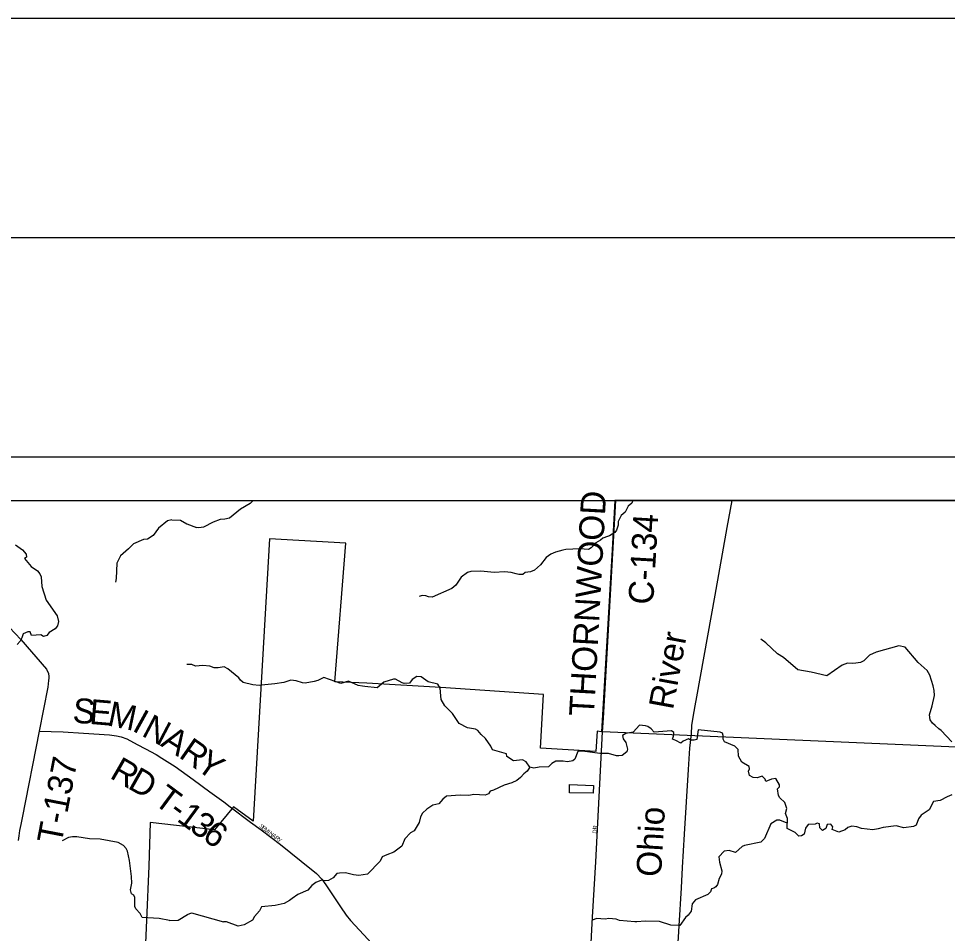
# Model space of a CAD drawing. Extents: x 0 to 40.4, y 0 to 22.
# Drawn here: x 5.767 to 7.886, y 19.912 to 22 of the extents above; entities that cross this region are included whole.
import ezdxf

# ---------------------------------------------------------------- set-up
doc = ezdxf.new("R2010")
doc.units = 0
for name, color, linetype in [('GM_X_City_Street', 7, 'Continuous'), ('GM_X_City_Street_Text', 7, 'Continuous'), ('GM_X_Corporation', 7, 'Continuous'), ('GM_X_County_Road', 7, 'Continuous'), ('GM_X_County_Road_Text', 7, 'Continuous'), ('GM_X_Minor_River', 7, 'Continuous'), ('GM_X_Rail_Line', 7, 'Continuous'), ('GM_X_Rail_Line_Text', 7, 'Continuous'), ('GM_X_Township', 7, 'Continuous'), ('GM_X_Township_Road', 7, 'Continuous'), ('GM_X_Township_Road_Text', 7, 'Continuous'), ('SH_Border', 7, 'Continuous'), ('SH_Cut_Line', 7, 'Continuous'), ('SH_Data', 7, 'Continuous')]:
    doc.layers.add(name, color=color, linetype=linetype)

msp = doc.modelspace()

# ---------------------------------------------------------------- linework, layer by layer
at = {"layer": 'GM_X_City_Street'}
for points in [[(7.0098, 19.1185), (7.0108, 19.1386), (7.0156, 19.1663), (7.0262, 19.2185), (7.0308, 19.2432), (7.0333, 19.26), (7.0351, 19.278), (7.0369, 19.3019), (7.0384, 19.3259), (7.0393, 19.3348), (7.0472, 19.4593), (7.0554, 19.5835), (7.0654, 19.7611), (7.0679, 19.7879), (7.0718, 19.8615), (7.0768, 19.9493), (7.0838, 20.0754), (7.0996, 20.3723), (7.1013, 20.4032)], [(6.2498, 20.2011), (6.296, 20.166), (6.3199, 20.1487), (6.364, 20.1154), (6.4116, 20.0767), (6.4466, 20.0492), (6.4587, 20.036), (6.4681, 20.0231), (6.4842, 19.9981), (6.5013, 19.9731), (6.5145, 19.9536), (6.5241, 19.9412), (6.5642, 19.8984), (6.594, 19.8649), (6.6301, 19.8274), (6.6555, 19.8037), (6.6684, 19.7925), (6.6763, 19.7881), (6.6859, 19.7856), (6.7077, 19.7856), (6.7817, 19.781), (7.0654, 19.7611)]]:
    msp.add_lwpolyline(points, dxfattribs=at)
at = {"layer": 'GM_X_Corporation'}
msp.add_line((8.7711, 20.9), (7.1277, 20.9), dxfattribs=at)
for points in [[(7.1277, 20.9), (7.121, 20.7872), (7.0967, 20.3722), (7.0871, 20.3735), (7.0838, 20.3271), (6.9581, 20.335), (6.9643, 20.4576), (6.7301, 20.4733), (6.5615, 20.4832), (6.4882, 20.4861), (6.5131, 20.8029), (6.3391, 20.8124), (6.3023, 20.1685), (6.2571, 20.201), (6.2135, 20.1483), (6.067, 20.1652), (6.0642, 20.0658), (6.0532, 19.8193)], [(7.078, 20.2322), (7.0238, 20.2329), (7.0237, 20.2519), (7.0791, 20.2493), (7.078, 20.2322)]]:
    msp.add_lwpolyline(points, dxfattribs=at)
at = {"layer": 'GM_X_County_Road'}
msp.add_lwpolyline([(7.1013, 20.4032), (7.1294, 20.9)], dxfattribs=at)
at = {"layer": 'GM_X_Minor_River'}
for points in [[(6.302, 20.9), (6.2952, 20.8936), (6.2732, 20.8807), (6.2482, 20.8598), (6.2376, 20.8572), (6.227, 20.8564), (6.2107, 20.8503), (6.1883, 20.8393), (6.1777, 20.8378), (6.1728, 20.8385)], [(7.1683, 20.9), (7.1665, 20.8939), (7.1581, 20.8871), (7.1509, 20.8738), (7.1415, 20.8659), (7.1347, 20.8522), (7.1347, 20.8435), (7.1313, 20.8325), (7.1271, 20.8272), (7.1154, 20.8196), (7.1104, 20.8181), (7.1002, 20.8139), (7.0949, 20.8093), (7.0843, 20.8036), (7.0733, 20.7922), (7.0676, 20.7884), (7.0476, 20.7896), (7.0157, 20.788), (7.0089, 20.7865), (6.9919, 20.7823), (6.9812, 20.7777), (6.9706, 20.7701), (6.9574, 20.7534), (6.9438, 20.7409), (6.9347, 20.7375), (6.9229, 20.7356), (6.9176, 20.7314), (6.9085, 20.731), (6.9025, 20.7325), (6.8907, 20.7359), (6.8759, 20.737), (6.8517, 20.7359), (6.8217, 20.7385), (6.799, 20.7381), (6.791, 20.7358), (6.7766, 20.7255), (6.7645, 20.7069), (6.7554, 20.6994), (6.7107, 20.6796), (6.702, 20.6803), (6.6963, 20.6826), (6.688, 20.683), (6.6812, 20.6814)], [(6.1165, 20.8559), (6.1063, 20.854), (6.0858, 20.8368), (6.0737, 20.8205), (6.0609, 20.8121), (6.0518, 20.811), (6.0287, 20.8014), (6.0174, 20.79), (5.9992, 20.7736), (5.9905, 20.7573), (5.9894, 20.7224), (5.9879, 20.714)], [(6.1165, 20.8559), (6.136, 20.8555), (6.1504, 20.8465), (6.1728, 20.8385)], [(5.7597, 20.7993), (5.7753, 20.7875), (5.784, 20.7777), (5.7848, 20.7708), (5.7799, 20.7678), (5.7954, 20.7496), (5.8099, 20.7398), (5.8152, 20.733), (5.8178, 20.7258), (5.8194, 20.7041), (5.8297, 20.673), (5.8544, 20.637), (5.8578, 20.6238), (5.8552, 20.6139), (5.8503, 20.607), (5.8362, 20.5987), (5.8313, 20.5922), (5.8234, 20.5899), (5.8173, 20.5937), (5.7961, 20.5917), (5.7934, 20.6001), (5.7874, 20.6001), (5.7772, 20.5955), (5.7738, 20.5867), (5.7704, 20.5791), (5.7632, 20.5715)], [(7.8962, 20.3497), (7.8723, 20.3751), (7.867, 20.3789), (7.8582, 20.3865), (7.8522, 20.3921), (7.8472, 20.3997), (7.8453, 20.4107), (7.8518, 20.4312), (7.857, 20.4551), (7.8566, 20.4664), (7.854, 20.477), (7.8464, 20.5013), (7.8399, 20.5123), (7.8194, 20.5305), (7.7902, 20.5653), (7.7754, 20.5687), (7.7239, 20.5538), (7.7088, 20.547), (7.6955, 20.5341), (7.6879, 20.5303), (7.6773, 20.5291), (7.6709, 20.5284), (7.6584, 20.5287), (7.6462, 20.5242), (7.6114, 20.4999), (7.5754, 20.5082), (7.5454, 20.5138), (7.5124, 20.5418), (7.4984, 20.5498), (7.4719, 20.5755), (7.4609, 20.5835)], [(6.9336, 20.2913), (6.9252, 20.3034), (6.9165, 20.308), (6.8961, 20.306), (6.8809, 20.3155), (6.8801, 20.3216), (6.8479, 20.331), (6.8445, 20.3393), (6.8323, 20.3571), (6.8221, 20.3658), (6.8145, 20.3749), (6.8096, 20.378), (6.7914, 20.3814), (6.772, 20.3908), (6.7572, 20.4139), (6.7398, 20.4313), (6.7311, 20.4461), (6.7303, 20.4541), (6.7288, 20.4715), (6.7238, 20.4806), (6.7015, 20.4862), (6.6855, 20.4976), (6.6753, 20.4983), (6.6647, 20.4919), (6.6586, 20.4835), (6.6469, 20.4828), (6.642, 20.4839), (6.6272, 20.4922), (6.6222, 20.4926), (6.5999, 20.4854), (6.5851, 20.4725), (6.5567, 20.4755), (6.5518, 20.4762), (6.5415, 20.4781), (6.5192, 20.4879), (6.5017, 20.4826), (6.4631, 20.4958), (6.4498, 20.4894), (6.4415, 20.4871), (6.4203, 20.4836), (6.4149, 20.484), (6.4002, 20.4889), (6.388, 20.4897), (6.3717, 20.4851), (6.3517, 20.4817), (6.321, 20.479), (6.3157, 20.4782), (6.3013, 20.4793), (6.2793, 20.4846), (6.2728, 20.4903), (6.2694, 20.4956), (6.2444, 20.516), (6.2356, 20.5202), (6.222, 20.5179), (6.2129, 20.5182), (6.2031, 20.5224), (6.1871, 20.5239), (6.1701, 20.522), (6.1621, 20.5258), (6.1507, 20.5261)], [(7.2833, 20.3505), (7.2784, 20.3463), (7.267, 20.3527), (7.2587, 20.3554), (7.2614, 20.3622), (7.2621, 20.3709), (7.2568, 20.3743), (7.217, 20.3713), (7.2106, 20.3788), (7.203, 20.3845), (7.1977, 20.386), (7.184, 20.3871), (7.1696, 20.3716), (7.1526, 20.3681), (7.145, 20.3636), (7.1461, 20.3564), (7.1526, 20.3477), (7.1564, 20.3329), (7.1549, 20.3268), (7.1443, 20.3185), (7.1367, 20.3173), (7.131, 20.3177), (7.1132, 20.323), (7.0935, 20.3226), (7.0533, 20.3278), (7.0431, 20.3275), (7.0363, 20.31), (7.0314, 20.3058), (7.0192, 20.3035), (7.0098, 20.3054), (6.9931, 20.3054), (6.9836, 20.3001), (6.976, 20.2921), (6.9548, 20.2913), (6.9423, 20.289), (6.9336, 20.2913), (6.9275, 20.2822), (6.92, 20.2761), (6.912, 20.2678), (6.9037, 20.2613), (6.8927, 20.2556), (6.8749, 20.2503), (6.8506, 20.2389), (6.8427, 20.2366), (6.8393, 20.2309), (6.8313, 20.2275), (6.8059, 20.229), (6.7942, 20.2271), (6.7745, 20.2274), (6.7434, 20.2251), (6.7351, 20.2183), (6.726, 20.208), (6.7123, 20.205), (6.698, 20.1955), (6.6885, 20.1868), (6.684, 20.1784), (6.6806, 20.1651), (6.6692, 20.1462), (6.6609, 20.1416), (6.6484, 20.1276), (6.6412, 20.1109), (6.6234, 20.0972), (6.6067, 20.0915), (6.5965, 20.087), (6.592, 20.0771), (6.5632, 20.0471), (6.5435, 20.0444), (6.5306, 20.0456), (6.5124, 20.0501), (6.4988, 20.0497), (6.4931, 20.0485), (6.4847, 20.0387), (6.4738, 20.033), (6.4677, 20.0318), (6.4582, 20.0333), (6.445, 20.0284), (6.4362, 20.0216), (6.4264, 20.0109), (6.4037, 20.001), (6.3912, 19.9916), (6.3847, 19.9874), (6.3726, 19.9802), (6.3525, 19.9756), (6.3211, 19.9725), (6.3165, 19.9634), (6.3052, 19.9505), (6.3003, 19.9422), (6.2817, 19.9319), (6.2681, 19.9289), (6.2411, 19.9383), (6.2343, 19.9383)], [(7.8963, 20.228), (7.8857, 20.2239), (7.8702, 20.2151), (7.8546, 20.2128), (7.8448, 20.1942), (7.8262, 20.1817), (7.8202, 20.1734), (7.8149, 20.159), (7.8088, 20.1559), (7.7872, 20.1529), (7.7694, 20.1574), (7.7402, 20.1536), (7.7281, 20.1505), (7.7164, 20.1486), (7.6906, 20.1516), (7.68, 20.1554), (7.6682, 20.1569), (7.6595, 20.1535), (7.6531, 20.1485), (7.639, 20.1432), (7.6235, 20.1496), (7.6246, 20.1557), (7.6205, 20.1614), (7.6121, 20.1606), (7.6091, 20.1519), (7.6015, 20.1469), (7.5955, 20.153), (7.5947, 20.1621), (7.5894, 20.1636), (7.5845, 20.1613), (7.5689, 20.1605), (7.5625, 20.1522), (7.5595, 20.1389), (7.5534, 20.1351), (7.5473, 20.1344), (7.539, 20.1427), (7.5204, 20.1518), (7.5215, 20.1741), (7.5166, 20.1859), (7.52, 20.1973), (7.5154, 20.2109), (7.504, 20.2215), (7.5006, 20.2268), (7.4983, 20.2423), (7.5033, 20.2465), (7.5036, 20.2514), (7.4945, 20.2655), (7.4847, 20.2639), (7.4718, 20.259), (7.4707, 20.2639), (7.4638, 20.2711), (7.4521, 20.2669), (7.443, 20.2681), (7.435, 20.2726), (7.4324, 20.2821), (7.4346, 20.2878), (7.4342, 20.2934), (7.4176, 20.3033), (7.4096, 20.3169), (7.4092, 20.3321), (7.4016, 20.3396), (7.3777, 20.3491), (7.3747, 20.3552), (7.375, 20.3639), (7.3731, 20.3688), (7.3675, 20.3714), (7.3174, 20.3767), (7.3148, 20.3543), (7.3084, 20.3528), (7.3004, 20.3535), (7.2955, 20.3562), (7.2833, 20.3505)], [(7.521, 20.1634), (7.5041, 20.1703), (7.4969, 20.1707), (7.4836, 20.162), (7.4693, 20.1286), (7.4609, 20.1206), (7.4234, 20.113), (7.4177, 20.1107), (7.403, 20.097), (7.3886, 20.1016), (7.3772, 20.1), (7.3651, 20.0871), (7.3662, 20.0746), (7.3716, 20.0553), (7.3708, 20.0473), (7.3655, 20.0371), (7.3614, 20.0238), (7.3583, 20.0181), (7.3534, 20.0151), (7.3481, 20.014), (7.3455, 20.0067), (7.3394, 20.0007), (7.3117, 19.9889), (7.3042, 19.9798), (7.3015, 19.9631), (7.2951, 19.954), (7.2887, 19.9483), (7.2754, 19.9305), (7.255, 19.9312), (7.2296, 19.9391), (7.1966, 19.9398), (7.178, 19.9387), (7.1727, 19.9387), (7.1382, 19.9413), (7.1303, 19.9443), (7.1136, 19.9462), (7.1052, 19.9447), (7.0855, 19.9458), (7.0768, 19.942)], [(6.1113, 19.9416), (6.0871, 19.9461), (6.0488, 19.9482), (6.0439, 19.9577), (6.0344, 19.9683), (6.0317, 19.9736), (6.0317, 19.9938), (6.0294, 19.9991), (6.0245, 20.0028), (6.0222, 20.0119), (6.0248, 20.0268), (6.0244, 20.0419), (6.0198, 20.0784), (6.0152, 20.0996), (6.0121, 20.1057), (6.0057, 20.1125), (5.9936, 20.1197), (5.9526, 20.1272), (5.9288, 20.1279), (5.8996, 20.1327), (5.8897, 20.1327), (5.8803, 20.1308), (5.8663, 20.1235)], [(6.11, 19.9418), (6.1309, 19.9427), (6.1521, 19.9556), (6.1612, 19.9587), (6.2343, 19.9383)]]:
    msp.add_lwpolyline(points, dxfattribs=at)
at = {"layer": 'GM_X_Rail_Line'}
msp.add_lwpolyline([(7.2637, 19.7516), (7.2743, 19.9291), (7.2794, 20.0159), (7.2821, 20.0624), (7.2867, 20.1383), (7.2955, 20.2862), (7.2987, 20.335), (7.3021, 20.3674), (7.3033, 20.3863), (7.3061, 20.4059), (7.3107, 20.4316), (7.3147, 20.4524), (7.3566, 20.6838), (7.3839, 20.8383), (7.3949, 20.9)], dxfattribs=at)
at = {"layer": 'GM_X_Township'}
for points in [[(8.1712, 20.3261), (7.0996, 20.3723), (7.1292, 20.9)], [(7.1292, 20.9), (7.1292, 20.9)]]:
    msp.add_lwpolyline(points, dxfattribs=at)
at = {"layer": 'GM_X_Township_Road'}
for points in [[(5.6413, 20.7196), (5.7721, 20.5826), (5.8301, 20.5151), (5.8351, 20.5051), (5.8356, 20.4986), (5.8356, 20.4944), (5.8348, 20.4891), (5.8332, 20.4744), (5.8137, 20.3738), (5.7744, 20.176), (5.772, 20.1604), (5.7686, 20.1472), (5.767, 20.1346), (5.7654, 20.1244)], [(5.8137, 20.3738), (5.8685, 20.3718), (5.9149, 20.3688), (5.9741, 20.365), (5.9897, 20.363), (6.0004, 20.3605), (6.0138, 20.356), (6.0373, 20.3431), (6.0566, 20.3336), (6.0804, 20.3202), (6.0933, 20.312), (6.1238, 20.2933), (6.1647, 20.263), (6.2032, 20.2355), (6.2349, 20.2125), (6.2498, 20.2011)]]:
    msp.add_lwpolyline(points, dxfattribs=at)
at = {"layer": 'SH_Border'}
msp.add_lwpolyline([(2, 21.5), (33.5, 21.5), (33.5, 0.5), (2, 0.5)], close=True, dxfattribs=at)
at = {"layer": 'SH_Cut_Line'}
msp.add_lwpolyline([(0, 0), (34, 0), (34, 22), (0, 22)], close=True, dxfattribs=at)
at = {"layer": 'SH_Data'}
for p, q in [((2.5, 21), (9.5, 21)), ((2.6, 20.9), (9.4, 20.9))]:
    msp.add_line(p, q, dxfattribs=at)

# ---------------------------------------------------------------- texts
at = {"layer": 'GM_X_City_Street_Text'}
for s, rotation, p in [('S', 319.2535, (6.3148, 20.1559)), ('E', 321.3536, (6.3202, 20.1513)), ('M', 322.7291, (6.3256, 20.147)), ('I', 322.7535, (6.3335, 20.1409)), ('N', 322.7649, (6.3368, 20.1384)), ('DR', 86.9884, (7.086, 20.1397)), ('A', 322.7673, (6.3435, 20.1334)), ('R', 322.7512, (6.3501, 20.1283)), ('Y', 322.7649, (6.3561, 20.1238))]:
    msp.add_text(s, height=0.00947, rotation=rotation, dxfattribs=at).set_placement(p)
at = {"layer": 'GM_X_County_Road_Text'}
for s, rotation, p in [('THORNWOOD', 86.8494, (7.0796, 20.4066)), ('C-134', 86.6819, (7.2147, 20.6614))]:
    msp.add_text(s, height=0.05682, rotation=rotation, dxfattribs=at).set_placement(p)
at = {"layer": 'GM_X_Rail_Line_Text'}
for s, rotation, p in [('River', 79.5525, (7.26, 20.4208)), ('Ohio', 86.6543, (7.2327, 20.04))]:
    msp.add_text(s, height=0.05663, rotation=rotation, dxfattribs=at).set_placement(p)
at = {"layer": 'GM_X_Township_Road_Text'}
for s, height, rotation, p in [('S', 0.0568, 355.3098, (5.8886, 20.3935)), ('E', 0.0568, 355.2549, (5.9268, 20.3904)), ('M', 0.0568, 348.1728, (5.9673, 20.3872)), ('I', 0.0568, 331.0917, (6.0235, 20.3761)), ('N', 0.0568, 332.2838, (6.0451, 20.3642)), ('A', 0.0568, 327.6992, (6.0883, 20.3415)), ('R', 0.0568, 325.1874, (6.13, 20.3152)), ('Y', 0.0568, 324.5699, (6.1682, 20.2886)), ('T-137', 0.05682, 79.1164, (5.8642, 20.1138)), ('R', 0.0568, 330.108, (5.9724, 20.2681)), ('D', 0.0568, 330.6014, (6.0133, 20.2446)), ('T', 0.0568, 323.431, (6.0724, 20.2095)), ('1', 0.0568, 323.6326, (6.1254, 20.1702)), ('-', 0.0568, 323.4747, (6.1065, 20.1842)), ('3', 0.0568, 323.9998, (6.1539, 20.1492)), ('6', 0.0568, 325.008, (6.1831, 20.128))]:
    msp.add_text(s, height=height, rotation=rotation, dxfattribs=at).set_placement(p)

doc.saveas('drawing.dxf')
